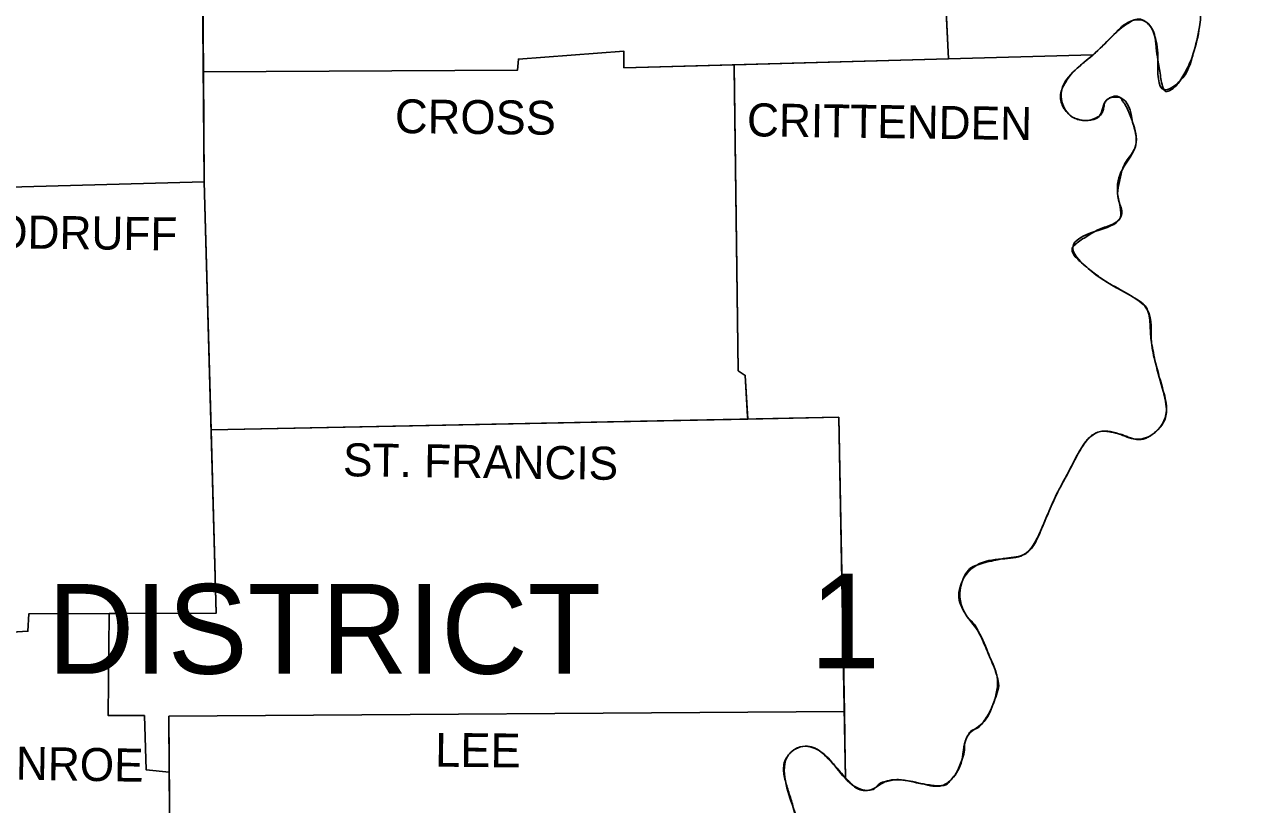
# Model space of a CAD drawing. Extents: x 1370567 to 1373900, y 377514 to 379648.
# Drawn here: x 1373603.6 to 1373765.8, y 379135.2 to 379238.7 of the extents above; entities that cross this region are included whole.
import ezdxf

# ---------------------------------------------------------------- set-up
doc = ezdxf.new("R2010")
doc.units = 0
doc.layers.add('Survey Names', color=7, linetype='Continuous')
doc.layers.add('Survey Symbols', color=7, linetype='Continuous')

msp = doc.modelspace()

# ---------------------------------------------------------------- linework, layer by layer
at = {"layer": 'Survey Names'}
for points in [[(1373577.53, 379400.68), (1373577.14, 379397.52), (1373579.23, 379397.21), (1373579.12, 379395.96), (1373581.52, 379395.43), (1373581.73, 379393.76), (1373582.88, 379393.03), (1373583.2, 379388.02), (1373589.15, 379387.39), (1373589.15, 379382.91), (1373591.34, 379382.59), (1373591.34, 379380.82), (1373593.22, 379380.3), (1373593.11, 379374.24), (1373594.79, 379373.93), (1373595.2, 379360.25), (1373586.33, 379359.41), (1373586.43, 379356.49), (1373583.72, 379356.39), (1373584.66, 379302.51), (1373626.74, 379301.57), (1373627.47, 379217.83), (1373600.01, 379217.1), (1373599.46, 379231.83)], [(1373722.25, 379322.76), (1373724.05, 379276.93), (1373726.17, 379234.16)], [(1373627.34, 379232.44), (1373669.02, 379232.66), (1373669.13, 379234.12), (1373683.12, 379235.17), (1373683.12, 379232.97), (1373745.31, 379234.68)], [(1373697.73, 379233.38), (1373698.26, 379192.78), (1373699.2, 379192.15), (1373699.53, 379186.37)], [(1373697.74, 379232.97), (1373698.26, 379192.78), (1373699.2, 379192.15), (1373699.51, 379186.72)], [(1373697.74, 379232.97), (1373698.26, 379192.78), (1373699.2, 379192.15), (1373699.51, 379186.72)], [(1373697.74, 379232.97), (1373698.26, 379192.78), (1373699.2, 379192.15), (1373699.51, 379186.72)], [(1373697.74, 379232.97), (1373698.26, 379192.78), (1373699.2, 379192.15), (1373699.51, 379186.72)], [(1373627.47, 379217.83), (1373629.03, 379160.62), (1373604.18, 379160.51), (1373604.08, 379158.22), (1373596.87, 379157.8), (1373596.25, 379145.9), (1373586.35, 379145.9)], [(1373628.37, 379184.94), (1373711.62, 379186.62)], [(1373711.62, 379186.62), (1373712.46, 379140.88)], [(1373711.62, 379186.62), (1373712.46, 379140.88)], [(1373711.62, 379186.62), (1373712.46, 379140.88)], [(1373711.62, 379186.62), (1373712.46, 379140.88)], [(1373711.62, 379186.62), (1373712.46, 379140.88)], [(1373711.62, 379186.62), (1373712.46, 379140.88)], [(1373711.62, 379186.62), (1373712.46, 379140.88)], [(1373711.62, 379186.62), (1373712.5, 379138.79)], [(1373614.84, 379160.56), (1373614.73, 379147.04), (1373619.53, 379147.04), (1373619.74, 379139.84), (1373622.82, 379139.52)], [(1373627.12, 379054.33), (1373636.86, 379054.96), (1373636.76, 379076.15), (1373629.14, 379076.67), (1373629.55, 379118.12), (1373622.98, 379119.06), (1373622.77, 379146.94), (1373712.34, 379147.57)]]:
    msp.add_lwpolyline(points, dxfattribs=at)
for points in [[(1373790.35, 379326.21), (1373791.5, 379326.32), (1373795.05, 379322.56), (1373796.61, 379319.42), (1373798.91, 379317.65), (1373801.52, 379316.71), (1373803.5, 379314.31), (1373804.86, 379311.7), (1373804.13, 379309.4), (1373801.21, 379309.19), (1373797.97, 379308.67), (1373794.84, 379308.77), (1373792.33, 379306.69), (1373794.63, 379303.87), (1373797.66, 379301.26), (1373798.49, 379298.44), (1373796.82, 379295.72), (1373793.48, 379294.26), (1373790.24, 379293.01), (1373787.32, 379290.5), (1373785.96, 379288.1), (1373782.73, 379287.06), (1373779.39, 379286.12), (1373776.46, 379285.8), (1373773.12, 379285.18), (1373769.88, 379283.61), (1373768.53, 379280.9), (1373768.94, 379277.03), (1373768.84, 379272.96), (1373772.29, 379271.6), (1373775.31, 379271.5), (1373778.24, 379269.93), (1373777.92, 379267.64), (1373775.73, 379264.71), (1373773.12, 379262.42), (1373770.51, 379261.27), (1373768.11, 379259.08), (1373768.94, 379256.88), (1373771.14, 379255.42), (1373772.7, 379253.02), (1373772.49, 379250.83), (1373769.99, 379249.26), (1373767.27, 379249.89), (1373765.29, 379252.5), (1373762.99, 379253.33), (1373761.01, 379254.27), (1373758.71, 379252.92), (1373758.71, 379249.89), (1373757.88, 379246.65), (1373758.61, 379244.25), (1373759.55, 379240.91), (1373759.44, 379238.4), (1373758.61, 379234.85), (1373756.83, 379231.2), (1373754.74, 379230.05), (1373753.91, 379234.02), (1373753.49, 379237.25), (1373752.24, 379239.13), (1373750.57, 379239.24), (1373748.37, 379237.67), (1373745.97, 379235.27), (1373742.95, 379232.66), (1373741.17, 379230.05), (1373742.11, 379226.81), (1373744.41, 379225.98), (1373746.18, 379226.6), (1373747.12, 379228.69), (1373748.9, 379229.01), (1373750.57, 379225.77)], [(1373750.57, 379225.77), (1373750.99, 379222.74), (1373749.21, 379219.5), (1373748.58, 379216.27), (1373748.9, 379213.03), (1373745.56, 379211.26), (1373742.63, 379209.17), (1373744.3, 379206.66), (1373747.44, 379204.37), (1373750.57, 379202.59), (1373752.55, 379200.82), (1373753.07, 379196.53), (1373753.6, 379193.82), (1373754.64, 379190.06), (1373755.06, 379187.45), (1373753.18, 379184.32), (1373750.99, 379183.69), (1373748.69, 379184.42), (1373745.97, 379184.63), (1373743.78, 379182.54), (1373742.21, 379179.62), (1373740.65, 379176.7), (1373739.5, 379174.19), (1373738.35, 379171.48), (1373736.05, 379168.34), (1373733.24, 379167.82), (1373729.89, 379166.99), (1373727.91, 379164.69), (1373728.22, 379160.83), (1373730.1, 379158.22), (1373731.56, 379154.98), (1373732.61, 379152.16), (1373732.09, 379148.61), (1373730.62, 379146), (1373728.75, 379144.43), (1373727.91, 379141.09), (1373726.55, 379138.59), (1373725.3, 379137.75), (1373722.79, 379137.96), (1373720.08, 379138.48), (1373717.78, 379138.27), (1373715.59, 379137.13), (1373713.4, 379137.86), (1373711.1, 379140.36), (1373709.22, 379142.24), (1373707.13, 379142.97), (1373704.94, 379141.82), (1373704.52, 379138.38), (1373705.57, 379134.83), (1373706.51, 379130.03), (1373705.57, 379127.1), (1373705.25, 379122.3)]]:
    msp.add_spline(points, degree=3, dxfattribs=at)
at = {"layer": 'Survey Symbols'}
for p, q in [((1373726.17, 379234.16), (1373724.05, 379276.93)), ((1373626.97, 379274.72), (1373627.34, 379232.44)), ((1373726.17, 379234.16), (1373745.31, 379234.68)), ((1373627.34, 379232.44), (1373627.47, 379217.83)), ((1373697.73, 379233.38), (1373697.74, 379232.97)), ((1373697.74, 379232.97), (1373697.73, 379233.37)), ((1373697.74, 379232.97), (1373698.26, 379192.78)), ((1373698.26, 379192.78), (1373697.74, 379232.97)), ((1373627.47, 379217.83), (1373628.37, 379184.94)), ((1373628.37, 379184.94), (1373627.47, 379217.83)), ((1373698.26, 379192.78), (1373699.2, 379192.15)), ((1373699.2, 379192.15), (1373698.26, 379192.78)), ((1373699.2, 379192.15), (1373699.51, 379186.72)), ((1373699.51, 379186.72), (1373699.2, 379192.15)), ((1373628.37, 379184.94), (1373699.53, 379186.37)), ((1373699.53, 379186.37), (1373628.37, 379184.94)), ((1373699.51, 379186.72), (1373699.53, 379186.37)), ((1373699.53, 379186.37), (1373699.51, 379186.72)), ((1373699.53, 379186.37), (1373711.62, 379186.62)), ((1373711.62, 379186.62), (1373699.53, 379186.37)), ((1373711.62, 379186.62), (1373712.34, 379147.57)), ((1373712.34, 379147.57), (1373711.62, 379186.62)), ((1373604.08, 379158.22), (1373604.18, 379160.51)), ((1373604.18, 379160.51), (1373614.84, 379160.56)), ((1373596.87, 379157.8), (1373604.08, 379158.22)), ((1373619.74, 379139.84), (1373619.53, 379147.04)), ((1373622.77, 379146.94), (1373712.34, 379147.57)), ((1373712.34, 379147.57), (1373622.77, 379146.94)), ((1373622.82, 379139.52), (1373622.77, 379146.94)), ((1373622.77, 379146.94), (1373622.82, 379139.52)), ((1373712.34, 379147.57), (1373712.46, 379140.88)), ((1373712.46, 379140.88), (1373712.34, 379147.57)), ((1373622.82, 379139.52), (1373619.74, 379139.84)), ((1373712.46, 379140.88), (1373712.5, 379138.79)), ((1373712.5, 379138.79), (1373712.46, 379140.88)), ((1373622.98, 379119.06), (1373622.82, 379139.52))]:
    msp.add_line(p, q, dxfattribs=at)
for points in [[(1373722.25, 379322.76), (1373724.05, 379276.93), (1373726.17, 379234.16)], [(1373599.46, 379231.83), (1373600.01, 379217.1), (1373627.47, 379217.83), (1373627.34, 379232.44), (1373626.97, 379274.72), (1373626.74, 379301.57), (1373603.52, 379302.09)], [(1373627.34, 379232.44), (1373669.02, 379232.66), (1373669.13, 379234.12), (1373683.12, 379235.17), (1373683.12, 379232.97), (1373726.17, 379234.16)], [(1373697.73, 379233.37), (1373683.12, 379232.97), (1373683.12, 379235.17), (1373669.13, 379234.12), (1373669.02, 379232.66), (1373627.34, 379232.44)], [(1373745.31, 379234.68), (1373726.17, 379234.16), (1373697.73, 379233.38)], [(1373745.31, 379234.68), (1373745.32, 379234.68)], [(1373745.32, 379234.68), (1373745.31, 379234.68)], [(1373627.47, 379217.83), (1373600.01, 379217.1), (1373599.46, 379231.83)], [(1373628.37, 379184.94), (1373629.03, 379160.62), (1373614.84, 379160.56)], [(1373614.84, 379160.56), (1373629.03, 379160.62), (1373628.37, 379184.94)], [(1373614.84, 379160.56), (1373604.18, 379160.51), (1373604.08, 379158.22), (1373596.87, 379157.8), (1373596.25, 379145.9), (1373586.35, 379145.9)], [(1373614.84, 379160.56), (1373614.73, 379147.04), (1373619.53, 379147.04), (1373619.74, 379139.84), (1373622.82, 379139.52)], [(1373619.53, 379147.04), (1373614.73, 379147.04), (1373614.84, 379160.56)], [(1373622.82, 379139.52), (1373622.98, 379119.06), (1373629.55, 379118.12), (1373629.41, 379103.39)]]:
    msp.add_lwpolyline(points, dxfattribs=at)
for points in [[(1373745.32, 379234.68), (1373745.97, 379235.27), (1373748.37, 379237.67), (1373749.43, 379238.52), (1373750, 379238.9), (1373750.57, 379239.24), (1373751.4, 379239.43), (1373752.24, 379239.13), (1373752.69, 379238.73), (1373753.05, 379238.28), (1373753.33, 379237.79), (1373753.49, 379237.25), (1373753.62, 379236.45), (1373753.71, 379235.64), (1373753.91, 379234.02), (1373754.25, 379232.01), (1373754.74, 379230.05), (1373754.89, 379229.86), (1373755.11, 379229.82), (1373755.72, 379230.08), (1373756.83, 379231.2), (1373757.36, 379232.09), (1373757.85, 379232.98), (1373758.27, 379233.9), (1373758.61, 379234.85), (1373759.44, 379238.4), (1373759.55, 379240.91), (1373758.61, 379244.25), (1373757.88, 379246.65), (1373757.87, 379247.46), (1373758.13, 379248.27), (1373758.47, 379249.08), (1373758.71, 379249.89), (1373758.73, 379250.26), (1373758.67, 379250.63), (1373758.49, 379251.4), (1373758.42, 379252.16), (1373758.71, 379252.92), (1373758.97, 379253.24), (1373759.23, 379253.53), (1373759.8, 379254.02), (1373761.01, 379254.27), (1373761.92, 379253.87), (1373762.84, 379253.4)], [(1373750.57, 379225.77), (1373749.89, 379227.49), (1373749.44, 379228.28), (1373749.18, 379228.65), (1373748.9, 379229.01), (1373748.51, 379229.2), (1373748.02, 379229.17), (1373747.52, 379228.97), (1373747.12, 379228.69), (1373746.85, 379228.22), (1373746.72, 379227.64), (1373746.56, 379227.06), (1373746.18, 379226.6), (1373745.74, 379226.35), (1373745.3, 379226.15), (1373744.85, 379226.02), (1373744.41, 379225.98), (1373743.83, 379226.01), (1373743.26, 379226.13), (1373742.68, 379226.39), (1373742.11, 379226.81), (1373741.92, 379227), (1373741.75, 379227.19), (1373741.46, 379227.59), (1373741.09, 379228.43), (1373740.99, 379229.27), (1373741.17, 379230.05), (1373741.5, 379230.73), (1373741.91, 379231.42), (1373742.95, 379232.66), (1373744.13, 379233.69), (1373745.32, 379234.68)], [(1373733.54, 379167.88), (1373734.8, 379168.04), (1373736.05, 379168.34), (1373736.28, 379168.45), (1373736.49, 379168.58), (1373736.86, 379168.88), (1373737.47, 379169.66), (1373737.95, 379170.56), (1373738.35, 379171.48), (1373739.5, 379174.19), (1373740.65, 379176.7), (1373742.21, 379179.62), (1373743.78, 379182.54), (1373744.69, 379183.79), (1373745.97, 379184.63), (1373746.3, 379184.72), (1373746.64, 379184.76), (1373747.33, 379184.71), (1373748.69, 379184.42), (1373749.26, 379184.26), (1373749.84, 379184.04), (1373750.41, 379183.83), (1373750.99, 379183.69), (1373751.53, 379183.66), (1373752.08, 379183.75), (1373752.63, 379183.97), (1373753.18, 379184.32), (1373753.59, 379184.67), (1373753.97, 379185.03), (1373754.57, 379185.78), (1373754.94, 379186.59), (1373755.06, 379187.45), (1373755.01, 379188.1), (1373754.92, 379188.76), (1373754.64, 379190.06), (1373753.6, 379193.82), (1373753.32, 379195.18), (1373753.07, 379196.53), (1373752.95, 379197.6), (1373752.9, 379198.68), (1373752.8, 379199.75), (1373752.55, 379200.82), (1373752.41, 379201.12), (1373752.22, 379201.39), (1373751.73, 379201.85), (1373750.57, 379202.59), (1373749.79, 379203.05), (1373749, 379203.48), (1373748.21, 379203.91), (1373747.44, 379204.37), (1373745.84, 379205.45), (1373744.3, 379206.66), (1373742.97, 379207.91), (1373742.56, 379208.59), (1373742.63, 379209.17), (1373742.89, 379209.46), (1373743.21, 379209.74), (1373743.94, 379210.26), (1373744.75, 379210.77), (1373745.56, 379211.26), (1373745.97, 379211.48), (1373746.41, 379211.66), (1373747.3, 379211.96), (1373748.16, 379212.35), (1373748.9, 379213.03), (1373749.02, 379213.22), (1373749.09, 379213.42), (1373749.15, 379213.82), (1373748.97, 379214.63), (1373748.68, 379215.46), (1373748.58, 379216.27), (1373748.83, 379217.89), (1373749.21, 379219.5), (1373749.6, 379220.35), (1373750.14, 379221.14), (1373750.66, 379221.92), (1373750.99, 379222.74), (1373750.57, 379225.77)], [(1373705.25, 379122.3), (1373705.57, 379127.1), (1373705.75, 379127.85), (1373706.09, 379128.57), (1373706.39, 379129.29), (1373706.51, 379130.03), (1373706.46, 379130.62), (1373706.38, 379131.22), (1373706.15, 379132.43), (1373705.57, 379134.83), (1373705.32, 379135.72), (1373705.04, 379136.61), (1373704.77, 379137.49), (1373704.52, 379138.38), (1373704.28, 379140.1), (1373704.45, 379140.97), (1373704.94, 379141.82), (1373705.19, 379142.1), (1373705.45, 379142.34), (1373705.99, 379142.7), (1373707.13, 379142.97), (1373707.67, 379142.93), (1373708.21, 379142.8), (1373708.74, 379142.57), (1373709.22, 379142.24), (1373710.19, 379141.31), (1373711.1, 379140.36), (1373712.5, 379138.79)]]:
    msp.add_spline(points, degree=3, dxfattribs=at)
msp.add_open_spline([(1373712.5, 379138.79), (1373712.78, 379138.48), (1373713.07, 379138.16), (1373713.4, 379137.86), (1373713.99, 379137.3), (1373714.89, 379137.05), (1373715.59, 379137.13), (1373716.34, 379137.21), (1373716.98, 379138.12), (1373717.78, 379138.27), (1373718.53, 379138.42), (1373719.32, 379138.58), (1373720.08, 379138.48), (1373720.99, 379138.37), (1373721.89, 379138.11), (1373722.79, 379137.96), (1373723.62, 379137.83), (1373724.47, 379137.69), (1373725.3, 379137.75), (1373725.8, 379137.79), (1373726.21, 379138.17), (1373726.55, 379138.59), (1373727.2, 379139.38), (1373727.55, 379140.22), (1373727.91, 379141.09), (1373728.35, 379142.15), (1373728.19, 379143.43), (1373728.75, 379144.43), (1373729.14, 379145.15), (1373730.14, 379145.34), (1373730.62, 379146), (1373731.22, 379146.81), (1373731.72, 379147.65), (1373732.09, 379148.61), (1373732.52, 379149.77), (1373732.93, 379151.03), (1373732.61, 379152.16), (1373732.34, 379153.11), (1373731.96, 379154.05), (1373731.56, 379154.98), (1373731.1, 379156.08), (1373730.61, 379157.15), (1373730.1, 379158.22), (1373729.64, 379159.18), (1373728.75, 379159.9), (1373728.22, 379160.83), (1373727.59, 379161.95), (1373727.43, 379163.48), (1373727.91, 379164.69), (1373728.28, 379165.63), (1373728.92, 379166.64), (1373729.89, 379166.99), (1373731, 379167.38), (1373732.11, 379167.58), (1373733.24, 379167.82), (1373733.34, 379167.84), (1373733.44, 379167.86), (1373733.54, 379167.88)], degree=3, dxfattribs=at)

# ---------------------------------------------------------------- texts
at = {"layer": 'Survey Names'}
for s, height, rotation, p in [('CROSS', 4.489, 359.384, (1373652.73, 379224.31)), ('CRITTENDEN', 4.386, 359.213, (1373699.41, 379223.89)), ('WOODRUFF', 4.384, 359.2748, (1373589.36, 379209.17)), ('ST. FRANCIS', 4.3845, 359.2216, (1373645.84, 379178.79)), ('LEE', 4.49, 359.4327, (1373658.06, 379140.26)), ('MONROE', 4.384, 359.0331, (1373593.01, 379138.69))]:
    msp.add_text(s, height=height, rotation=rotation, dxfattribs=at).set_placement(p)
for s, height, p in [('1', 12.53, (1373707.76, 379153.31)), ('DISTRICT', 11.903, (1373606.69, 379152.58))]:
    msp.add_text(s, height=height, dxfattribs=at).set_placement(p)

doc.saveas('drawing.dxf')
